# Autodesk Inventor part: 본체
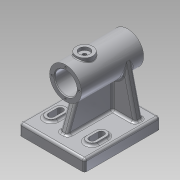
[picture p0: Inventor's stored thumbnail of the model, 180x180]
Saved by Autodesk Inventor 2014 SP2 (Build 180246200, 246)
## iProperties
Created: 2022-06
Part Number: 본체
Material: 알루미늄 6061
Document SubType Name: Modeling
Designer: 거성
Density: 2.71 g/cm^3
Appearance: 알루미늄 - 평지
Mass: 633.96 g
Surface Area: 512.727 cm^2
Volume: 233.934 cm^3
Author: 거성
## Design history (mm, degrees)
sketch "스케치1"
  geometry: L1 (0, 41)-(0, -41); L2 (14.5, 41)-(14.5, -21); L3 (14.5, -21)-(11.5, -21); L4 (11.5, -21)-(11.5, -41); L5 (11.5, -41)-(21, -41); L6 (21, -41)-(21, 41); L7 (21, 41)-(14.5, 41); 2 further points
  constraints: 14 end point, 5 parallel, 2 horizontal alignment, 1 coincident, 1 midpoint, 1 perpendicular, 1 vertical
  dimensions: "d0" = 82 distance of L1.start L1.end; "d1" = 29 diameter of L2 L1; "d2" = 23 diameter of L4 L1; "d3" = 42 diameter of L6 L1; "d4" = 62 distance of L2.start L2.end
revolve "회전1" sketch "스케치1" stored, may be unused: angle "d5" = 90 deg
node "작업 평면1"
sketch "스케치2"
  geometry: L1 (43, 59)-(-43, 59); L2 (-43, 59)-(-43, -41); L3 (-43, -41)-(43, -41); L4 (43, -41)-(43, 59); L5 (43, 59)-(-43, -41); L6 (-43, 59)-(43, -41); L7 (-21, 41)-(21, 41) reference; 3 further points
  constraints: 12 end point, 3 midpoint, 2 parallel, 1 horizontal, 1 perpendicular, 1 vertical alignment
  dimensions: "d7" = 86 distance of L3.end L2.end; "d8" = 100 distance of L2.end L1.end; "d9" = 18 distance between parallel lines of L1 L7
extrude "돌출1" join sketch "스케치2" distance "d10" = 15; taper "d11" = 0 deg
fillet "모깎기1" dims "d12" = 3
node "작업 평면2"
sketch "스케치3"
  geometry: L1 (-40, -57)-(40, -57) reference; L2 (-20.441, 4.814)-(-35, -57); L3 (20.441, 4.814)-(35, -57); L4 (43, -60)-(43, -72) reference; L5 (-43, -72)-(-43, -60) reference; C1 r 14.5 at (0, 0) reference; A1 r 21 centre (0, 0) between (-20.441, 4.814) and (20.441, 4.814) reference; 1 further point
  constraints: 4 end point, 2 point on circle, 2 point on line, 1 horizontal alignment, 1 tangent
  dimensions: "d14" = 8 distance from line of L4 L3.end; "d15" = 8 distance from line of L5 L2.end
extrude "돌출2" join sketch "스케치3" distance "d16" = 10; taper "d17" = 0 deg
node "작업 평면3"
sketch "스케치4"
  geometry: L1 (14.5, 41)-(21, 41) reference; L2 (21, 41)-(21, -41) reference; L3 (21, -41)-(11.5, -41) reference; L4 (11.5, -41)-(11.5, -21) reference; L5 (11.5, -21)-(14.5, -21) reference; L6 (14.5, -21)-(14.5, 41) reference; L7 (-57, 56)-(-57, -16) reference; L8 (-57, -16)-(-21, -16) reference; L9 (-21, -16)-(-21, 41) reference; L10 (-21, 41)-(-14.5, 41) reference; L11 (-14.5, 41)-(-14.5, -21) reference; L12 (-14.5, -21)-(-11.5, -21) reference; L13 (-11.5, -21)-(-11.5, -41) reference; L14 (-11.5, -41)-(-21, -41) reference; L15 (-21, -41)-(-21, -26) reference; L16 (-21, -26)-(-57, -26) reference; L17 (-57, -26)-(-57, -38) reference; L18 (-60, -41)-(-72, -41) reference; L19 (-72, -41)-(-72, 59) reference; L20 (-72, 59)-(-60, 59) reference; L21 (-57, 56)-(-57, -38) reference; L22 (-21, 41)-(-21, -41) reference; L23 (-57, 44)-(-21, 30.897); A1 r 3 centre (-60, 56) between (-57, 56) and (-60, 59) reference; A2 r 3 centre (-60, -38) between (-60, -41) and (-57, -38) reference; 1 further point
  constraints: 2 end point, 2 point on line
  dimensions: "d19" = 70 deg angle of L7 L23; "d20" = 15 distance from line of L23.start L20
feature "리브1" sketch "스케치4" dims "d21" = 1, "d22" = 10, "d23" = 0, "d24" = 0, "d25" = 1, "d26" = 1
fillet "모깎기2" dims "d27" = 3
fillet "모깎기3" dims "d28" = 3
node "작업 평면4"
sketch "스케치5"
  geometry: L1 (-21, 41)-(21, 41) reference; C1 r 11 at (0, 16); C2 r 7 at (0, 16); 1 further point
  constraints: 2 centre point, 1 coincident, 1 vertical alignment
  dimensions: "d30" = 22 diameter of C1; "d31" = 14 diameter of C2; "d32" = 25 distance from line of C2.centre L1
node "작업 평면5"
sketch "스케치6"
  geometry: L1 (-27, -33)-(-27, -21); L2 (-20, -33)-(-20, -21); L3 (-34, -21)-(-34, -33); L4 (-27, -33)-(-27, -21); L5 (-23, -33)-(-23, -21); L6 (-31, -21)-(-31, -33); L7 (-40, -59)-(40, -59) reference; A1 r 7 centre (-27, -33) between (-34, -33) and (-20, -33); A2 r 7 centre (-27, -21) between (-20, -21) and (-34, -21); A3 r 4 centre (-27, -33) between (-31, -33) and (-23, -33); A4 r 4 centre (-27, -21) between (-23, -21) and (-31, -21); 3 further points
  constraints: 16 end point, 8 point on circle, 8 tangent, 4 centre point, 3 equal length, 2 midpoint, 1 vertical
  dimensions: "d42" = 12 distance of L1.start L1.end; "d43" = 14 diameter of A2; "d44" = 8 diameter of A4; "d45" = 27 horizontal distance of point (0, 0) point (-27, -27); "d63" = 26 distance from line of L7 L1.start
extrude "돌출5" join sketch "스케치6" stored distance "d47" = 10; taper "d48" = 0 deg
extrude "돌출6" cut sketch "스케치6" stored distance "d49" = 10; taper "d50" = 0 deg
fillet "모깎기5" dims "d51" = 3
sketch "스케치7"
  geometry: L1 (-40, -56)-(-40, 38) reference; L2 (27, -33)-(27, -21); L3 (34, -33)-(34, -21); L4 (20, -21)-(20, -33); L5 (27, -33)-(27, -21); L6 (31, -33)-(31, -21); L7 (23, -21)-(23, -33); L8 (-40, -59)-(40, -59) reference; A1 r 7 centre (27, -33) between (20, -33) and (34, -33); A2 r 7 centre (27, -21) between (34, -21) and (20, -21); A3 r 4 centre (27, -33) between (23, -33) and (31, -33); A4 r 4 centre (27, -21) between (31, -21) and (23, -21); 3 further points
  constraints: 16 end point, 8 point on circle, 8 tangent, 4 centre point, 3 parallel, 2 midpoint, 1 collinear
  dimensions: "d52" = 12 distance of L2.start L2.end; "d53" = 14 diameter of A2; "d54" = 8 diameter of A4; "d55" = 27 horizontal distance of point (0, 0) point (27, -27); "d57" = 26 distance from line of L8 L2.start
extrude "돌출7" join sketch "스케치7" distance "d58" = 3; taper "d59" = 0 deg
extrude "돌출8" cut sketch "스케치7" stored distance "d60" = 3; taper "d61" = 0 deg
fillet "모깎기6" dims "d62" = 3
sketch "스케치8" dims "d64" = 36
  geometry: L1 (0, 0)-(0, 18); C1 r 21 at (0, 0) reference; 1 further point
  constraints: 2 coincident, 2 end point, 1 vertical, 1 vertical alignment, 2 other
hole "구멍1" sketch "스케치8" at (0, 18) diameter "d65" = 2.459; stored, may be unused: countersink angle "d69" = 90 deg, drill point angle "d71" = 118 deg; dims "d66" = 8, "d67" = 4, "d68" = 2, "d70" = 10
sketch "스케치9" dims "d75" = 36
  geometry: L1 (0, 0)-(0, 18); C1 r 21 at (0, 0) reference
  constraints: 2 end point, 1 coincident, 1 vertical, 1 vertical alignment, 2 other
hole "구멍2" sketch "스케치9" at (0, 18) diameter "d76" = 2.459; stored, may be unused: countersink angle "d80" = 90 deg, drill point angle "d82" = 118 deg; dims "d77" = 8, "d78" = 4, "d79" = 2, "d81" = 10
sketch "스케치10"
  geometry: L1 (0, 0)-(80, 0) reference; 2 further points
  constraints: 1 vertical alignment, 1 other
  dimensions: "d86" = 6 distance from line of L1 point (40, 6)
feature "엠보싱1" sketch "스케치10" dims "d0" = 82, "d1" = 29, "d2" = 23, "d3" = 42, "d4" = 62, "d87" = 0.5, "d88" = 0
chamfer "모따기1" distance "d89" = 1; stored, may be unused: second distance "d90" = 2, angle "d91" = 45 deg
chamfer "모따기2" distance "d92" = 1; stored, may be unused: second distance "d93" = 2, angle "d94" = 45 deg
extrude "돌출9" join sketch "스케치5" stored distance "d95" = 4; taper "d96" = 0 deg
sketch "스케치11"
  geometry: C1 r 11 at (0, 0) reference; C2 r 7 at (0, 0); 1 further point
  constraints: 1 centre point, 1 coincident
  dimensions: "d97" = 14 diameter of C2
extrude "돌출10" cut sketch "스케치11" distance "d98" = 4; taper "d99" = 0 deg
sketch "스케치12"
  geometry: C1 r 7 at (0, 0) reference; 2 further points
  constraints: 1 coincident
hole "구멍3" sketch "스케치12" at (0, 0) diameter "d100" = 4.917; stored, may be unused: countersink angle "d104" = 90 deg, drill point angle "d106" = 0 deg; dims "d101" = 8, "d102" = 4, "d103" = 2, "d105" = 6
fillet "모깎기7" dims "d107" = 1
node "솔리드1"
pattern_circular "원형 패턴1" dims angle "d73" = 360 deg
pattern_circular "원형 패턴2" dims angle "d84" = 360 deg
node "투영된 루프1"
node "절단 모서리 투영1"
other parameters: "d6" = -72, "d13" = -15, "d18" = 0, "d29" = 24, "d38" = 3
